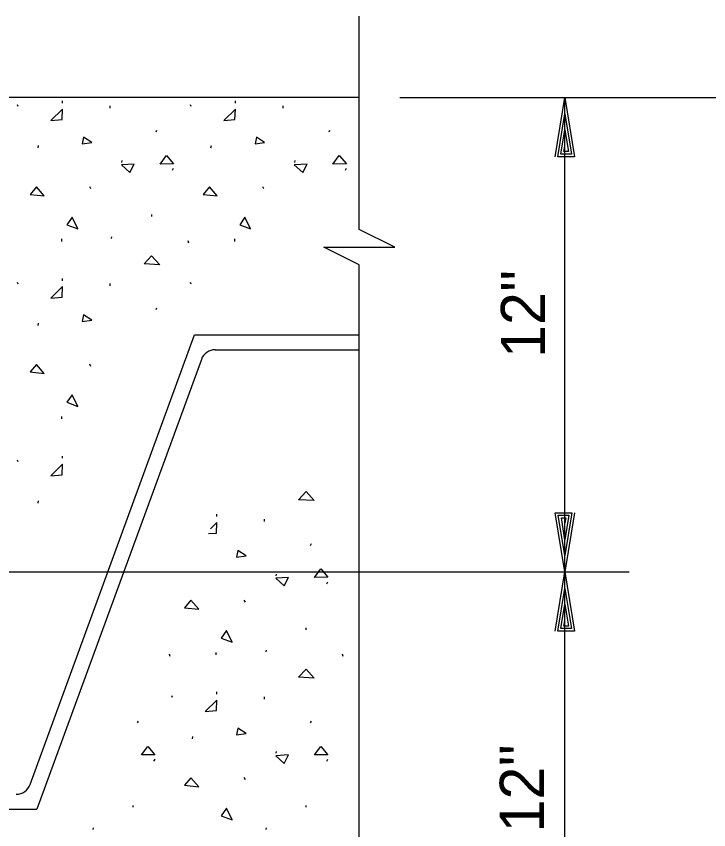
# Model space of a CAD drawing. Extents: x 22369.6 to 22384.3, y 22369.6 to 22381.8.
# Drawn here: x 22373.292 to 22374.021, y 22378.84 to 22379.697 of the extents above; entities that cross this region are included whole.
import ezdxf

# ---------------------------------------------------------------- set-up
doc = ezdxf.new("R2010")
doc.units = 0
for name, color, linetype in [('Level 1', 7, 'Continuous'), ('Level 10', 7, 'Continuous'), ('Level 4', 7, 'Continuous'), ('Level 8', 7, 'Continuous')]:
    doc.layers.add(name, color=color, linetype=linetype)

msp = doc.modelspace()

# ---------------------------------------------------------------- linework, layer by layer
at = {"layer": 'Level 1'}
for p, q in [((22373.65295, 22379.4725), (22373.65295, 22379.697)), ((22373.69555, 22379.61141), (22374.32633, 22379.61141)), ((22373.86956, 22379.61141), (22373.86956, 22379.61141)), ((22373.86956, 22379.11166), (22373.86956, 22379.61141)), ((22373.86956, 22379.59408), (22373.86956, 22379.59408)), ((22373.65295, 22378.7964), (22373.65295, 22379.43512)), ((22373.30624, 22378.88777), (22373.47939, 22379.36141)), ((22373.47939, 22379.36141), (22373.65295, 22379.36141)), ((22373.50123, 22379.34581), (22373.65295, 22379.34581)), ((22373.48657, 22379.33556), (22373.31339, 22378.86191)), ((22373.86956, 22379.129), (22373.86956, 22379.129)), ((22373.05064, 22379.11166), (22373.93723, 22379.11166)), ((22373.86956, 22378.61191), (22373.86956, 22379.11166)), ((22373.86956, 22379.11166), (22373.86956, 22379.11166)), ((22373.86956, 22379.11166), (22373.86956, 22379.11166)), ((22373.86956, 22379.09433), (22373.86956, 22379.09433)), ((22373.03426, 22378.86191), (22373.31339, 22378.86191))]:
    msp.add_line(p, q, dxfattribs=at)
for points in [[(22373.85923, 22379.54908), (22373.86956, 22379.61141), (22373.87989, 22379.54908), (22373.86223, 22379.54908), (22373.86956, 22379.59408), (22373.87656, 22379.55175), (22373.86523, 22379.55175), (22373.86956, 22379.57741), (22373.87323, 22379.55441), (22373.86856, 22379.55441), (22373.86956, 22379.56008)], [(22373.65295, 22379.43512), (22373.61545, 22379.45375), (22373.69036, 22379.45375), (22373.65295, 22379.4725)], [(22373.87989, 22379.174), (22373.86956, 22379.11166), (22373.85923, 22379.174), (22373.87689, 22379.174), (22373.86956, 22379.129), (22373.86256, 22379.17133), (22373.87389, 22379.17133), (22373.86956, 22379.14566), (22373.86589, 22379.16866), (22373.87056, 22379.16866), (22373.86956, 22379.163)], [(22373.85923, 22379.04933), (22373.86956, 22379.11166), (22373.87989, 22379.04933), (22373.86223, 22379.04933), (22373.86956, 22379.09433), (22373.87656, 22379.052), (22373.86523, 22379.052), (22373.86956, 22379.07766), (22373.87323, 22379.05466), (22373.86856, 22379.05466), (22373.86956, 22379.06033)]]:
    msp.add_lwpolyline(points, dxfattribs=at)
for centre, start, end in [((22373.50123, 22379.3302), 90, 159.92259), ((22373.29158, 22378.89313), 270, 339.91382)]:
    msp.add_arc(centre, 0.01561, start, end, dxfattribs=at)
at = {"layer": 'Level 10'}
msp.add_line((22373.65295, 22379.61141), (22372.35348, 22379.61141), dxfattribs=at)
at = {"layer": 'Level 8'}
for p, q in [((22373.29353, 22379.60181), (22373.29282, 22379.6036)), ((22373.3404, 22379.60548), (22373.3404, 22379.60781)), ((22373.39053, 22379.6001), (22373.39053, 22379.6026)), ((22373.47574, 22379.60181), (22373.47503, 22379.6036)), ((22373.52261, 22379.60548), (22373.52261, 22379.60781)), ((22373.57274, 22379.6001), (22373.57274, 22379.6026)), ((22373.4389, 22379.5751), (22373.43982, 22379.57706)), ((22373.62111, 22379.5751), (22373.62203, 22379.57706)), ((22373.31453, 22379.55831), (22373.3149, 22379.56073)), ((22373.49674, 22379.55831), (22373.49711, 22379.56073)), ((22373.4029, 22379.5431), (22373.40307, 22379.54494)), ((22373.58511, 22379.5431), (22373.58528, 22379.54494)), ((22373.45611, 22379.53477), (22373.45736, 22379.53685)), ((22373.63832, 22379.53477), (22373.63957, 22379.53685)), ((22373.37028, 22379.51527), (22373.36915, 22379.51748)), ((22373.55249, 22379.51527), (22373.55136, 22379.51748)), ((22373.43445, 22379.48623), (22373.43428, 22379.48827)), ((22373.33953, 22379.45989), (22373.33953, 22379.46239)), ((22373.39207, 22379.46285), (22373.3924, 22379.46473)), ((22373.47324, 22379.45789), (22373.47253, 22379.46039)), ((22373.52174, 22379.45989), (22373.52174, 22379.46239)), ((22373.29353, 22379.41477), (22373.29282, 22379.41656)), ((22373.3404, 22379.41844), (22373.3404, 22379.42077)), ((22373.39053, 22379.41306), (22373.39053, 22379.41556)), ((22373.47574, 22379.41477), (22373.47503, 22379.41656)), ((22373.31453, 22379.37127), (22373.3149, 22379.37369)), ((22373.37028, 22379.32823), (22373.36915, 22379.33044)), ((22373.33953, 22379.27285), (22373.33953, 22379.27535)), ((22373.3404, 22379.23139), (22373.3404, 22379.23373)), ((22373.29353, 22379.22773), (22373.29282, 22379.22952)), ((22373.31453, 22379.18423), (22373.3149, 22379.18664)), ((22373.50305, 22379.17005), (22373.50305, 22379.17238)), ((22373.55318, 22379.16468), (22373.55318, 22379.16718)), ((22373.60155, 22379.13968), (22373.60247, 22379.14163)), ((22373.56555, 22379.10768), (22373.56572, 22379.10951)), ((22373.61876, 22379.09934), (22373.62001, 22379.10143)), ((22373.53293, 22379.07984), (22373.5318, 22379.08205)), ((22373.59709, 22379.0508), (22373.59693, 22379.05284)), ((22373.55472, 22379.02743), (22373.55505, 22379.0293)), ((22373.45368, 22379.02247), (22373.45297, 22379.02497)), ((22373.50218, 22379.02447), (22373.50218, 22379.02697)), ((22373.63588, 22379.02247), (22373.63518, 22379.02497)), ((22373.50305, 22378.98301), (22373.50305, 22378.98534)), ((22373.45618, 22378.97934), (22373.45547, 22378.98113)), ((22373.55318, 22378.97763), (22373.55318, 22378.98013)), ((22373.41934, 22378.95263), (22373.42026, 22378.95459)), ((22373.60155, 22378.95263), (22373.60247, 22378.95459)), ((22373.47718, 22378.93584), (22373.47755, 22378.93826)), ((22373.56555, 22378.92063), (22373.56572, 22378.92247)), ((22373.43655, 22378.9123), (22373.4378, 22378.91438)), ((22373.61876, 22378.9123), (22373.62001, 22378.91438)), ((22373.53293, 22378.8928), (22373.5318, 22378.89501)), ((22373.41488, 22378.86376), (22373.41472, 22378.8658)), ((22373.59709, 22378.86376), (22373.59693, 22378.8658)), ((22373.37251, 22378.84038), (22373.37284, 22378.84226)), ((22373.55472, 22378.84038), (22373.55505, 22378.84226))]:
    msp.add_line(p, q, dxfattribs=at)
for points in [[(22373.33978, 22379.5881), (22373.3404, 22379.59923), (22373.32807, 22379.58719)], [(22373.52199, 22379.5881), (22373.52261, 22379.59923), (22373.51028, 22379.58719)], [(22373.3609, 22379.56269), (22373.37103, 22379.56398), (22373.36253, 22379.56969)], [(22373.54311, 22379.56269), (22373.55324, 22379.56398), (22373.54474, 22379.56969)], [(22373.44303, 22379.54135), (22373.44974, 22379.55023), (22373.45728, 22379.54169)], [(22373.62524, 22379.54135), (22373.63195, 22379.55023), (22373.63949, 22379.54169)], [(22373.40228, 22379.54039), (22373.41115, 22379.53248), (22373.4159, 22379.54135)], [(22373.58449, 22379.54039), (22373.59336, 22379.53248), (22373.59811, 22379.54135)], [(22373.32115, 22379.50777), (22373.3129, 22379.51727), (22373.30628, 22379.50939)], [(22373.50336, 22379.50777), (22373.49511, 22379.51727), (22373.48849, 22379.50939)], [(22373.34495, 22379.47739), (22373.35632, 22379.47298), (22373.35032, 22379.48527)], [(22373.52715, 22379.47739), (22373.53853, 22379.47298), (22373.53253, 22379.48527)], [(22373.42628, 22379.43619), (22373.4342, 22379.44477), (22373.4427, 22379.43527)], [(22373.33978, 22379.40106), (22373.3404, 22379.41219), (22373.32807, 22379.40014)], [(22373.3609, 22379.37564), (22373.37103, 22379.37694), (22373.36253, 22379.38264)], [(22373.32115, 22379.32073), (22373.3129, 22379.33023), (22373.30628, 22379.32235)], [(22373.34495, 22379.29035), (22373.35632, 22379.28594), (22373.35032, 22379.29823)], [(22373.33978, 22379.21402), (22373.3404, 22379.22514), (22373.32807, 22379.2131)], [(22373.58893, 22379.1878), (22373.59684, 22379.19638), (22373.60534, 22379.18688)], [(22373.52355, 22379.12726), (22373.53368, 22379.12855), (22373.52518, 22379.13426)], [(22373.60568, 22379.10593), (22373.61238, 22379.1148), (22373.61993, 22379.10626)], [(22373.56493, 22379.10497), (22373.5738, 22379.09705), (22373.57855, 22379.10593)], [(22373.4838, 22379.07234), (22373.47555, 22379.08184), (22373.46893, 22379.07397)], [(22373.50759, 22379.04197), (22373.51897, 22379.03755), (22373.51297, 22379.04984)], [(22373.58893, 22379.00076), (22373.59684, 22379.00934), (22373.60534, 22378.99984)], [(22373.50243, 22378.96563), (22373.50305, 22378.97676), (22373.49072, 22378.96472)], [(22373.52355, 22378.94022), (22373.53368, 22378.94151), (22373.52518, 22378.94722)], [(22373.42347, 22378.91888), (22373.43018, 22378.92776), (22373.43772, 22378.91922)], [(22373.60568, 22378.91888), (22373.61238, 22378.92776), (22373.61993, 22378.91922)], [(22373.56493, 22378.91793), (22373.5738, 22378.91001), (22373.57855, 22378.91888)], [(22373.4838, 22378.8853), (22373.47555, 22378.8948), (22373.46893, 22378.88693)], [(22373.50759, 22378.85493), (22373.51897, 22378.85051), (22373.51297, 22378.8628)]]:
    msp.add_lwpolyline(points, close=True, dxfattribs=at)
for points in [[(22373.4389, 22379.38806), (22373.43982, 22379.39002)], [(22373.50305, 22379.1638), (22373.49612, 22379.15703)], [(22373.50243, 22379.15268), (22373.50305, 22379.1638)], [(22373.49404, 22379.15202), (22373.50243, 22379.15268)]]:
    msp.add_lwpolyline(points, dxfattribs=at)

# ---------------------------------------------------------------- texts
at = {"layer": 'Level 4'}
for p in [(22373.84875, 22379.33704), (22373.84759, 22378.83728)]:
    msp.add_text("12''", height=0.046625, rotation=90, dxfattribs=at).set_placement(p)

doc.saveas('drawing.dxf')
